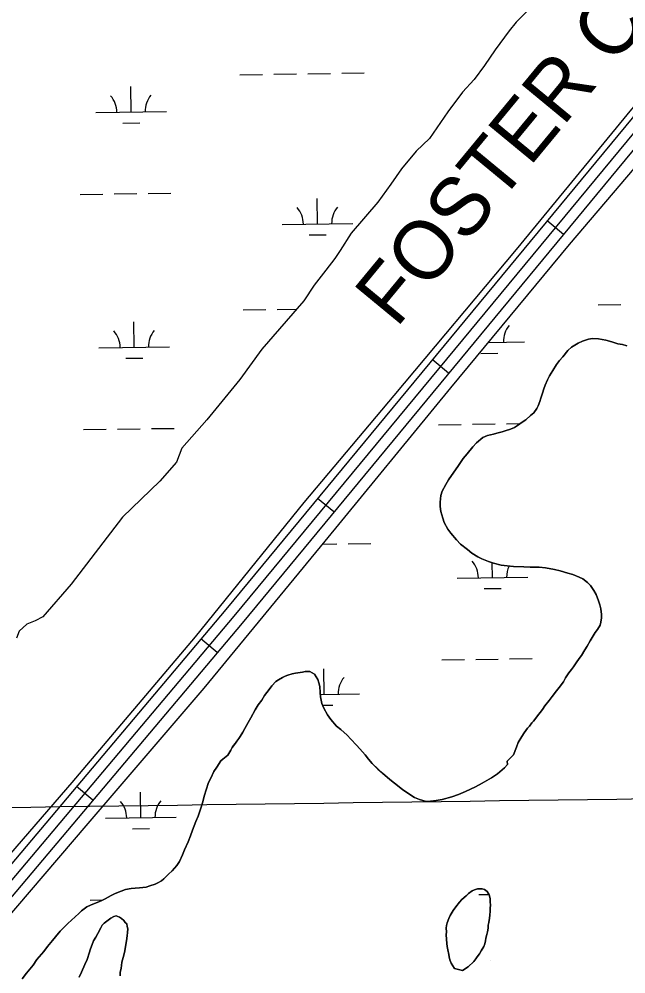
# Model space of a CAD drawing. Extents: x 3767014 to 3805179, y 361544 to 387384.
# Drawn here: x 3780968 to 3781825, y 372923 to 374273 of the extents above; entities that cross this region are included whole.
import ezdxf

# ---------------------------------------------------------------- set-up
doc = ezdxf.new("R2010")
doc.units = 0
for name, color, linetype in [('V-GRID-MAJR', 7, 'Continuous'), ('V-RIVR-IDEN', 7, 'Continuous'), ('V-ROAD-CNTR', 7, 'Continuous'), ('V-TOPO-SHOR', 7, 'Continuous'), ('V-WETL-SWMP', 7, 'Continuous')]:
    doc.layers.add(name, color=color, linetype=linetype)

msp = doc.modelspace()

# ---------------------------------------------------------------- linework, layer by layer
at = {"layer": 'V-GRID-MAJR'}
msp.add_spline([(3771169.95, 373025.6), (3773820.257, 373061.356), (3779120.863, 373133.445), (3784421.458, 373206.305), (3789722.043, 373279.937), (3795022.617, 373354.339), (3800323.181, 373429.512), (3802973.458, 373467.388)], degree=3, dxfattribs=at)
at = {"layer": 'V-ROAD-CNTR'}
for p, q in [((3781737.115, 373968.938), (3781713.992, 373988.051)), ((3781574.851, 373772.623), (3781551.728, 373791.736)), ((3781412.587, 373576.31), (3781389.464, 373595.423)), ((3781247.511, 373377.399), (3781224.569, 373396.728)), ((3781071.641, 373168.645), (3781048.698, 373187.974))]:
    msp.add_line(p, q, dxfattribs=at)
for points in [[(3782996.008, 375549.581), (3782070.95, 374419.915), (3781259.697, 373438.426), (3780556.215, 372603.406), (3780262.248, 372247.669), (3780020.473, 371935.287), (3779872.046, 371735.835), (3779803.549, 371623.461)], [(3783007.613, 375540.078), (3782082.534, 374410.385), (3781271.214, 373428.815), (3780567.732, 372593.796), (3780273.963, 372238.299), (3780032.422, 371926.218), (3779884.493, 371727.436), (3779816.357, 371615.654)], [(3783019.218, 375530.575), (3782094.118, 374400.855), (3781282.731, 373419.204), (3780579.249, 372584.186), (3780285.678, 372228.93), (3780044.371, 371917.149), (3779896.94, 371719.037), (3779829.165, 371607.847)], [(3781633.577, 372941.884), (3781633.577, 372941.884)]]:
    msp.add_lwpolyline(points, dxfattribs=at)
at = {"layer": 'V-TOPO-SHOR'}
for points in [[(3781687.181, 374286.085), (3781670.508, 374269.162), (3781660.483, 374256.846), (3781640.689, 374229.976), (3781625.632, 374207.759), (3781610.797, 374187.926), (3781594.419, 374170.041), (3781573.801, 374142.08), (3781548.005, 374104.54), (3781528.764, 374086.731), (3781508.061, 374061.634), (3781493.172, 374039.733), (3781474.533, 374014.426), (3781437.118, 373970.82), (3781421.522, 373946.23), (3781414.07, 373934.959), (3781401.225, 373918.258), (3781384.914, 373896.871), (3781370.021, 373874.81), (3781310.808, 373806.771), (3781279.608, 373763.482), (3781232.934, 373706.425), (3781197.688, 373666.741), (3781190.166, 373646.56), (3781166.718, 373619.944), (3781113.833, 373568.935), (3781041.197, 373474.184), (3781001.172, 373428.096), (3780990.203, 373422.488), (3780978.62, 373417.692), (3780967.858, 373407.782), (3780963.946, 373398.015)], [(3780018.581, 371950.259), (3780033.478, 371966.27), (3780045.985, 371982.185), (3780060.432, 371999.163), (3780088.952, 372037.428), (3780171.11, 372137.188), (3780262.123, 372259.482), (3780354.5, 372372.989), (3780473.141, 372511.126), (3780614.631, 372677.33), (3780714.029, 372797.658), (3780803.323, 372908.852), (3780910.522, 373041.556), (3781042.571, 373193.516), (3781216.921, 373399.622), (3781370.644, 373589.706), (3781497.896, 373740.834), (3781670.832, 373947.614), (3781833.678, 374145.897), (3781903.857, 374225.591), (3781920.876, 374243.62), (3781934.567, 374256.002), (3781951.979, 374270.833), (3781963.1, 374282.327)], [(3781701.369, 373726.637), (3781703.692, 373732.76), (3781705.045, 373737.362), (3781707.702, 373744.405), (3781709.397, 373750.236), (3781711.386, 373755.442), (3781714.683, 373763.396), (3781717.299, 373768.895), (3781722.132, 373776.5), (3781727.291, 373784.716), (3781731.768, 373790.475), (3781736.237, 373795.927), (3781743.572, 373804.705), (3781748.643, 373809.519), (3781758.058, 373814.844), (3781764.317, 373817.775), (3781772.431, 373820.659), (3781778.325, 373821.435), (3781786.666, 373821.22), (3781791.895, 373820.157), (3781797.126, 373819.096), (3781805.721, 373816.71), (3781814.317, 373814.324), (3781820.473, 373813.239), (3781826.605, 373811.225)], [(3781635.569, 373200.223), (3781643.755, 373205.888), (3781653.872, 373214.594), (3781658.009, 373219.124), (3781657.509, 373223.775), (3781666.709, 373232.815), (3781670.705, 373243.843), (3781673.342, 373250.268), (3781678.51, 373258.794), (3781681.733, 373263.965), (3781686.536, 373270.336), (3781689.397, 373273.353), (3781692.606, 373277.91), (3781694.832, 373280.326), (3781698.351, 373284.873), (3781700.593, 373287.906), (3781704.427, 373292.756), (3781707.628, 373297.001), (3781710.854, 373302.175), (3781716.916, 373309.441), (3781721.393, 373315.2), (3781727.477, 373323.392), (3781731.313, 373328.239), (3781737.082, 373336.13), (3781740.007, 373341.621), (3781744.832, 373348.916), (3781748.66, 373353.456), (3781751.543, 373357.403), (3781755.394, 373362.867), (3781759.569, 373368.945), (3781762.779, 373373.5), (3781767.614, 373381.107), (3781770.837, 373386.28), (3781775.052, 373393.9), (3781777.96, 373398.773), (3781782.161, 373405.777), (3781785.362, 373410.022), (3781788.919, 373416.115), (3781789.96, 373420.418), (3781791.045, 373426.572), (3781790.855, 373431.217), (3781789.827, 373439.282), (3781788.424, 373444.883), (3781786.722, 373450.802), (3781783.236, 373459.549), (3781780.289, 373465.189), (3781775.218, 373472.433), (3781770.995, 373476.56), (3781764.634, 373481.672), (3781759.444, 373484.279), (3781750.573, 373487.908), (3781743.513, 373489.943), (3781732.769, 373493.003), (3781724.467, 373494.762), (3781711.853, 373497.253), (3781702.909, 373498.101), (3781690.241, 373498.426), (3781681.281, 373498.658), (3781666.756, 373499.03), (3781657.511, 373500.196), (3781649.184, 373501.029), (3781638.123, 373503.788), (3781631.381, 373506.125), (3781621.899, 373510.079), (3781616.093, 373512.703), (3781607.884, 373518.171), (3781601.523, 373523.281), (3781591.826, 373530.95), (3781586.106, 373536.974), (3781577.994, 373546.149), (3781573.511, 373552.137), (3781568.495, 373561.544), (3781566.793, 373567.462), (3781563.949, 373577.121), (3781562.888, 373583.949), (3781562.738, 373590.138), (3781563.903, 373599.382), (3781565.917, 373605.514), (3781570.805, 373615.283), (3781574.688, 373621.986), (3781582.383, 373632.609), (3781587.843, 373640.508), (3781595.551, 373651.75), (3781600.989, 373658.721), (3781609.277, 373668.402), (3781614.37, 373674.147), (3781623.222, 373681.648), (3781629.781, 373684.264), (3781638.498, 373686.512), (3781643.171, 373687.938), (3781650.325, 373689.609), (3781655.001, 373691.034), (3781662.488, 373693.625), (3781667.805, 373695.962), (3781672.202, 373698.63), (3781678.819, 373703.408), (3781683.851, 373706.679), (3781690.806, 373712.684), (3781695.236, 373716.589), (3781699.411, 373722.668), (3781701.369, 373726.637)], [(3781089.032, 373029.387), (3781097.494, 373033.807), (3781103.443, 373036.746), (3781111.881, 373040.239), (3781117.808, 373042.251), (3781125.881, 373043.59), (3781131.775, 373044.364), (3781137.661, 373044.831), (3781146.963, 373045.83), (3781152.266, 373047.549), (3781159.745, 373049.828), (3781163.499, 373051.587), (3781168.832, 373054.543), (3781172.309, 373057.545), (3781178.656, 373063.875), (3781184.045, 373068.993), (3781190.725, 373076.241), (3781194.274, 373082.025), (3781198.538, 373091.501), (3781201.493, 373098.227), (3781206.431, 373109.849), (3781209.735, 373118.113), (3781212.723, 373126.073), (3781217.368, 373138.322), (3781220.657, 373145.967), (3781224.357, 373157.623), (3781226.711, 373164.981), (3781229.77, 373175.725), (3781232.132, 373183.395), (3781235.484, 373193.512), (3781238.732, 373199.613), (3781242.996, 373209.087), (3781247.18, 373215.472), (3781252.663, 373224.297), (3781255.817, 373226.691), (3781262.766, 373232.387), (3781266.966, 373239.389), (3781268.916, 373243.051), (3781270.841, 373245.785), (3781273.716, 373249.42), (3781275.332, 373252.16), (3781278.21, 373255.798), (3781280.143, 373258.841), (3781283.7, 373264.932), (3781286.617, 373270.113), (3781291.474, 373278.645), (3781295.349, 373285.039), (3781301.204, 373296.33), (3781305.714, 373303.323), (3781310.84, 373310.303), (3781314.715, 373316.697), (3781321.117, 373325.19), (3781324.652, 373330.355), (3781330.681, 373336.384), (3781334.454, 373338.76), (3781340.11, 373342.326), (3781343.866, 373344.085), (3781347.614, 373345.533), (3781353.848, 373347.538), (3781358.198, 373348.353), (3781364.719, 373349.422), (3781368.133, 373349.952), (3781372.176, 373350.776), (3781378.664, 373350.61), (3781385.058, 373346.735), (3781390.118, 373339.184), (3781391.245, 373334.826), (3781392.654, 373329.534), (3781393.057, 373321.174), (3781393.508, 373314.669), (3781395.433, 373305.345), (3781398.355, 373298.777), (3781403.678, 373289.362), (3781408.456, 373282.747), (3781416.259, 373273.58), (3781422.62, 373268.469), (3781431.381, 373260.514), (3781436.801, 373254.808), (3781444.628, 373246.567), (3781449.437, 373241.187), (3781456.637, 373232.653), (3781461.739, 373226.648), (3781466.843, 373220.644), (3781474.985, 373212.704), (3781481.33, 373206.973), (3781491.613, 373198.052), (3781498.277, 373192.625), (3781509.795, 373183.671), (3781517.084, 373178.537), (3781526.82, 373172.411), (3781533.554, 373169.763), (3781543.071, 373167.045), (3781549.197, 373167.197), (3781557.139, 373168.229), (3781565.53, 373169.87), (3781579.538, 373173.527), (3781588.893, 373176.687), (3781598.584, 373180.767), (3781612.982, 373187.509), (3781622.077, 373192.531), (3781635.569, 373200.223)], [(3781594.673, 372927.761), (3781602.539, 372933.125), (3781610.463, 372940.651), (3781613.338, 372944.287), (3781615.273, 372947.33), (3781618.474, 372951.575), (3781621.057, 372955.837), (3781624.606, 372961.621), (3781626.257, 372965.598), (3781626.986, 372969.907), (3781627.381, 372973.299), (3781628.751, 372978.521), (3781629.784, 372982.512), (3781630.535, 372987.749), (3781630.949, 372991.759), (3781631.67, 372995.761), (3781632.747, 373001.608), (3781633.169, 373005.925), (3781633.628, 373011.789), (3781633.716, 373015.186), (3781633.865, 373021.058), (3781633.638, 373024.157), (3781633.771, 373029.408), (3781632.362, 373034.702), (3781629.401, 373039.723), (3781625.446, 373042.3), (3781622.38, 373043.305), (3781615.575, 373043.172), (3781611.517, 373041.73), (3781608.079, 373040.272), (3781602.732, 373036.701), (3781599.553, 373033.381), (3781593.548, 373028.279), (3781590.044, 373024.349), (3781584.934, 373017.988), (3781581.092, 373012.831), (3781577.201, 373005.819), (3781574.92, 373001.239), (3781572.605, 372995.425), (3781571.882, 372991.423), (3781571.479, 372987.725), (3781571.653, 372982.463), (3781571.549, 372978.445), (3781572.007, 372972.25), (3781572.466, 372966.055), (3781572.974, 372961.713), (3781573.781, 372957.054), (3781575.159, 372950.527), (3781575.38, 372947.119), (3781576.507, 372942.761), (3781578.549, 372938.071), (3781580.625, 372934.616), (3781582.995, 372930.536), (3781594.673, 372927.761)], [(3780972.023, 372916.141), (3780978.102, 372924.024), (3780987.365, 372935.533), (3780992.823, 372943.433), (3781002.387, 372954.627), (3781007.822, 372961.598), (3781014.851, 372970.384), (3781019.002, 372975.535), (3781025.699, 372983.399), (3781030.152, 372988.233), (3781036.808, 372994.555), (3781041.237, 372998.46), (3781047.259, 373004.18), (3781051.688, 373008.086), (3781055.815, 373012.309), (3781063.383, 373017.988), (3781068.699, 373020.325), (3781074.325, 373022.653), (3781078.073, 373024.103), (3781084.633, 373026.717), (3781089.032, 373029.387)], [(3781119.711, 372993.596), (3781117.476, 372995.695), (3781115.385, 372998.593), (3781112.242, 373001.334), (3781109.387, 373003.386), (3781104.674, 373005.301), (3781101.434, 373004.334), (3781097.166, 373001.907), (3781093.511, 372999.218), (3781087.641, 372994.608), (3781084.975, 372991.894), (3781082.963, 372988.235), (3781078.732, 372979.995), (3781075.822, 372975.123), (3781072.9, 372969.633), (3781068.247, 372957.076), (3781067.233, 372953.701), (3781063.573, 372943.592), (3781060.599, 372936.246), (3781055.68, 372925.242), (3781052.405, 372918.216)], [(3781110.282, 372920.374), (3781110.339, 372925.072), (3781111.732, 372931.097), (3781112.391, 372935.099), (3781112.694, 372939.668), (3781115.672, 372949.609), (3781117.003, 372955.698), (3781118.472, 372964.689), (3781119.16, 372969.803), (3781120.204, 372976.764), (3781120.94, 372981.321), (3781121.079, 372986.699), (3781120.54, 372989.803), (3781119.711, 372993.596)]]:
    msp.add_lwpolyline(points, dxfattribs=at)
at = {"layer": 'V-WETL-SWMP'}
for p, q in [((3781279.674, 374194.754), (3781311.671, 374195.198)), ((3781327.669, 374195.42), (3781359.666, 374195.865)), ((3781375.665, 374196.087), (3781407.661, 374196.531)), ((3781423.66, 374196.754), (3781455.657, 374197.198)), ((3781125.801, 374141.869), (3781125.301, 374177.866)), ((3781075.806, 374141.175), (3781175.797, 374142.564)), ((3781577.666, 374148.146), (3781578.282, 374148.155)), ((3781114.017, 374126.273), (3781138.015, 374126.606)), ((3781054.004, 374025.429), (3781086.001, 374025.873)), ((3781101.999, 374026.095), (3781133.996, 374026.54)), ((3781149.995, 374026.762), (3781181.992, 374027.207)), ((3781389.461, 373983.654), (3781388.96, 374019.651)), ((3781339.465, 373982.96), (3781439.456, 373984.349)), ((3781377.676, 373968.058), (3781401.674, 373968.391)), ((3781786.154, 373869.082), (3781818.151, 373869.527)), ((3781284.295, 373862.111), (3781316.291, 373862.555)), ((3781332.29, 373862.777), (3781359.883, 373863.161)), ((3781130.422, 373809.226), (3781129.922, 373845.223)), ((3781631.211, 373816.183), (3781682.277, 373816.892)), ((3781632.282, 373816.198), (3781632.264, 373817.456)), ((3781080.427, 373808.532), (3781180.417, 373809.921)), ((3781620.497, 373800.602), (3781644.495, 373800.935)), ((3781118.638, 373793.63), (3781142.635, 373793.963)), ((3781058.625, 373692.786), (3781090.622, 373693.23)), ((3781106.62, 373693.453), (3781138.617, 373693.897)), ((3781154.615, 373694.119), (3781186.612, 373694.564)), ((3781560.484, 373699.757), (3781592.481, 373700.202)), ((3781608.48, 373700.424), (3781640.477, 373700.868)), ((3781656.475, 373701.091), (3781675.984, 373701.362)), ((3781397.107, 373530.971), (3781416.903, 373531.246)), ((3781432.902, 373531.468), (3781464.898, 373531.912)), ((3781636.903, 373483.555), (3781636.614, 373504.311)), ((3781586.908, 373482.86), (3781686.898, 373484.249)), ((3781625.118, 373467.959), (3781649.116, 373468.292)), ((3781565.105, 373367.114), (3781597.102, 373367.559)), ((3781613.1, 373367.781), (3781645.097, 373368.226)), ((3781661.096, 373368.448), (3781693.093, 373368.892)), ((3781398.702, 373318.368), (3781398.202, 373354.365)), ((3781393.257, 373318.293), (3781448.697, 373319.063)), ((3781396.517, 373302.906), (3781410.915, 373303.106)), ((3781139.664, 373143.941), (3781139.164, 373179.937)), ((3781089.669, 373143.246), (3781189.659, 373144.635)), ((3781127.879, 373128.344), (3781151.877, 373128.678)), ((3781601.014, 373034.906), (3781601.723, 373034.916)), ((3781617.721, 373035.138), (3781631.987, 373035.336)), ((3781067.866, 373027.5), (3781086.346, 373027.757))]:
    msp.add_line(p, q, dxfattribs=at)
for points in [[(3781687.181, 374286.084), (3781670.509, 374269.162), (3781660.483, 374256.845), (3781640.69, 374229.976), (3781625.633, 374207.76), (3781610.797, 374187.926), (3781594.419, 374170.042), (3781573.802, 374142.079), (3781548.004, 374104.54), (3781528.763, 374086.73), (3781508.061, 374061.635), (3781493.171, 374039.733), (3781474.533, 374014.426), (3781437.118, 373970.819), (3781421.523, 373946.229), (3781414.07, 373934.96), (3781401.224, 373918.258), (3781384.915, 373896.871), (3781370.021, 373874.81), (3781310.807, 373806.772), (3781279.609, 373763.483), (3781232.934, 373706.425), (3781197.689, 373666.741), (3781190.166, 373646.56), (3781166.719, 373619.944)], [(3780025.717, 371834.653), (3780056.527, 371895), (3780166.581, 372039.392), (3780290.996, 372202.544), (3780433.66, 372382.481), (3780595.159, 372572.811), (3780741.306, 372749.657), (3780921.136, 372967.272), (3781065.005, 373135.738), (3781228.964, 373326.942), (3781400.292, 373534.835), (3781578.045, 373751.941), (3781745.672, 373954.491), (3781888.974, 374122.784), (3782009.425, 374259.986), (3782010.435, 374249.773), (3782030.835, 374226.008), (3782094.59, 374167.381), (3782154.079, 374116.187), (3782194.889, 374081.391), (3782251.034, 374036.331), (3782277.797, 374012.402), (3782296.183, 373996.966), (3782313.044, 373984.117)], [(3781826.605, 373811.225), (3781820.473, 373813.238), (3781814.317, 373814.324), (3781805.721, 373816.709), (3781797.125, 373819.095), (3781791.896, 373820.157), (3781786.667, 373821.219), (3781778.324, 373821.434), (3781772.43, 373820.658), (3781764.316, 373817.775), (3781758.057, 373814.844), (3781748.644, 373809.52), (3781743.573, 373804.704), (3781736.236, 373795.926), (3781731.767, 373790.475), (3781727.29, 373784.716), (3781722.131, 373776.5), (3781717.298, 373768.895), (3781714.683, 373763.397), (3781711.386, 373755.442), (3781709.397, 373750.237), (3781707.701, 373744.406), (3781705.046, 373737.363), (3781703.691, 373732.76), (3781701.369, 373726.636), (3781699.412, 373722.667), (3781695.236, 373716.59), (3781690.806, 373712.684), (3781683.85, 373706.68), (3781678.818, 373703.408), (3781672.202, 373698.631), (3781667.805, 373695.961), (3781662.488, 373693.625), (3781655.001, 373691.035), (3781650.326, 373689.609), (3781643.172, 373687.938), (3781638.497, 373686.512), (3781629.782, 373684.263), (3781623.222, 373681.649), (3781614.371, 373674.147), (3781609.276, 373668.403), (3781600.988, 373658.722), (3781595.552, 373651.75), (3781587.842, 373640.509), (3781582.383, 373632.61), (3781574.689, 373621.986), (3781570.806, 373615.284), (3781565.917, 373605.515), (3781563.904, 373599.383), (3781562.738, 373590.137), (3781562.888, 373583.949), (3781563.949, 373577.12), (3781566.793, 373567.462), (3781568.496, 373561.543), (3781573.51, 373552.138), (3781577.994, 373546.148), (3781586.106, 373536.973), (3781591.826, 373530.951), (3781601.523, 373523.281), (3781607.884, 373518.17), (3781616.092, 373512.702), (3781621.899, 373510.079), (3781631.382, 373506.125), (3781638.124, 373503.787), (3781649.184, 373501.029), (3781657.511, 373500.196), (3781666.757, 373499.031), (3781681.28, 373498.657), (3781690.241, 373498.427), (3781702.909, 373498.101), (3781711.854, 373497.252), (3781724.467, 373494.763), (3781732.77, 373493.003), (3781743.513, 373489.944), (3781750.572, 373487.907), (3781759.445, 373484.278), (3781764.635, 373481.671), (3781770.996, 373476.56), (3781775.219, 373472.432), (3781780.289, 373465.19), (3781783.236, 373459.549), (3781786.721, 373450.801), (3781788.424, 373444.883), (3781789.826, 373439.281), (3781790.855, 373431.216), (3781791.045, 373426.573), (3781789.959, 373420.417), (3781788.92, 373416.115), (3781785.362, 373410.023), (3781782.161, 373405.776), (3781777.961, 373398.773), (3781775.053, 373393.901), (3781770.838, 373386.279), (3781767.613, 373381.106), (3781762.779, 373373.5), (3781759.57, 373368.945)], [(3781166.719, 373619.944), (3781113.833, 373568.935), (3781041.197, 373474.183), (3781001.172, 373428.096), (3780990.203, 373422.488), (3780978.619, 373417.693), (3780967.858, 373407.782), (3780963.946, 373398.014)], [(3781759.57, 373368.945), (3781755.394, 373362.868), (3781751.543, 373357.402), (3781748.659, 373353.457), (3781744.831, 373348.917), (3781740.006, 373341.621), (3781737.082, 373336.13), (3781731.313, 373328.24), (3781727.478, 373323.391), (3781721.393, 373315.2), (3781716.916, 373309.44), (3781710.854, 373302.175), (3781707.629, 373297.002), (3781704.428, 373292.756), (3781700.593, 373287.907), (3781698.35, 373284.873), (3781694.832, 373280.326), (3781692.606, 373277.909), (3781689.396, 373273.354), (3781686.536, 373270.336), (3781681.734, 373263.966), (3781678.509, 373258.793), (3781673.343, 373250.268), (3781670.704, 373243.843), (3781666.71, 373232.815), (3781657.51, 373223.776), (3781658.009, 373219.125), (3781653.873, 373214.593), (3781643.755, 373205.887), (3781635.57, 373200.223), (3781622.076, 373192.531), (3781612.981, 373187.509), (3781598.584, 373180.768), (3781588.894, 373176.688), (3781579.537, 373173.528), (3781565.529, 373169.869), (3781557.138, 373168.229), (3781549.196, 373167.197), (3781543.071, 373167.045), (3781533.555, 373169.764), (3781526.821, 373172.411), (3781517.085, 373178.536), (3781509.796, 373183.671), (3781498.277, 373192.624), (3781491.614, 373198.052), (3781481.331, 373206.974), (3781474.986, 373212.703), (3781466.842, 373220.643), (3781461.74, 373226.649), (3781456.638, 373232.654), (3781449.437, 373241.188), (3781444.628, 373246.568), (3781436.801, 373254.809), (3781431.382, 373260.514), (3781422.62, 373268.469), (3781416.259, 373273.58), (3781408.456, 373282.747), (3781403.679, 373289.363), (3781398.355, 373298.776), (3781395.432, 373305.344), (3781393.508, 373314.67), (3781393.057, 373321.174), (3781392.654, 373329.533), (3781391.244, 373334.826), (3781390.119, 373339.183), (3781385.057, 373346.734), (3781378.664, 373350.609), (3781372.175, 373350.776), (3781368.134, 373349.953), (3781364.719, 373349.422), (3781358.199, 373348.353), (3781353.849, 373347.537), (3781347.614, 373345.533), (3781343.866, 373344.084), (3781340.11, 373342.325), (3781334.453, 373338.761), (3781330.682, 373336.384), (3781324.652, 373330.355), (3781321.118, 373325.19), (3781314.715, 373316.697), (3781310.84, 373310.304), (3781305.714, 373303.324), (3781301.205, 373296.329), (3781295.349, 373285.039), (3781291.474, 373278.646), (3781286.617, 373270.113), (3781283.701, 373264.932), (3781280.143, 373258.84), (3781278.209, 373255.797), (3781275.333, 373252.161), (3781273.716, 373249.42), (3781270.84, 373245.784), (3781268.915, 373243.05), (3781266.965, 373239.39), (3781262.765, 373232.387), (3781255.817, 373226.691), (3781252.663, 373224.298), (3781247.18, 373215.473), (3781242.996, 373209.087), (3781238.732, 373199.612), (3781235.484, 373193.512)], [(3781235.484, 373193.512), (3781232.131, 373183.394), (3781229.77, 373175.725), (3781226.71, 373164.982), (3781224.357, 373157.622), (3781220.656, 373145.968), (3781217.367, 373138.323), (3781212.723, 373126.074), (3781209.735, 373118.112), (3781206.431, 373109.849), (3781201.494, 373098.226), (3781198.538, 373091.5), (3781194.275, 373082.025), (3781190.725, 373076.241), (3781184.045, 373068.993), (3781178.657, 373063.875), (3781172.31, 373057.545), (3781168.832, 373054.543), (3781163.5, 373051.588), (3781159.744, 373049.829), (3781152.265, 373047.548), (3781146.964, 373045.83), (3781137.662, 373044.832), (3781131.776, 373044.365), (3781125.881, 373043.589), (3781117.808, 373042.251), (3781111.881, 373040.239), (3781103.443, 373036.746), (3781097.493, 373033.807), (3781089.031, 373029.387), (3781084.633, 373026.717), (3781078.073, 373024.103), (3781074.325, 373022.654), (3781068.7, 373020.325), (3781063.383, 373017.988), (3781055.816, 373012.308), (3781051.688, 373008.086), (3781047.259, 373004.18), (3781041.237, 372998.46), (3781036.808, 372994.555), (3781030.152, 372988.233), (3781025.699, 372983.4), (3781019.003, 372975.534), (3781014.851, 372970.384), (3781007.823, 372961.598), (3781002.387, 372954.627), (3780992.823, 372943.432), (3780987.364, 372935.534), (3780978.101, 372924.023), (3780972.023, 372916.14)], [(3781052.406, 372918.216), (3781055.679, 372925.243), (3781060.6, 372936.247), (3781063.572, 372943.592), (3781067.233, 372953.701), (3781068.247, 372957.076), (3781072.899, 372969.633), (3781075.823, 372975.124), (3781078.732, 372979.996), (3781082.963, 372988.235), (3781084.974, 372991.894), (3781087.641, 372994.608), (3781093.511, 372999.219), (3781097.167, 373001.907), (3781101.434, 373004.333), (3781104.675, 373005.301), (3781109.387, 373003.386), (3781112.241, 373001.334), (3781115.386, 372998.594), (3781117.476, 372995.695), (3781119.71, 372993.597), (3781120.54, 372989.804), (3781121.078, 372986.698), (3781120.94, 372981.321), (3781120.204, 372976.764), (3781119.159, 372969.803), (3781118.471, 372964.688), (3781117.003, 372955.698), (3781115.672, 372949.61), (3781112.695, 372939.669), (3781112.392, 372935.1), (3781111.732, 372931.098), (3781110.34, 372925.073), (3781110.281, 372920.375)]]:
    msp.add_lwpolyline(points, dxfattribs=at)
msp.add_lwpolyline([(3781594.672, 372927.762), (3781582.994, 372930.536), (3781580.625, 372934.616), (3781578.549, 372938.071), (3781576.506, 372942.761), (3781575.381, 372947.119), (3781575.16, 372950.526), (3781573.782, 372957.054), (3781572.974, 372961.713), (3781572.467, 372966.055), (3781572.008, 372972.25), (3781571.549, 372978.446), (3781571.653, 372982.463), (3781571.479, 372987.724), (3781571.883, 372991.424), (3781572.605, 372995.425), (3781574.919, 373001.24), (3781577.201, 373005.819), (3781581.092, 373012.831), (3781584.935, 373017.988), (3781590.045, 373024.35), (3781593.548, 373028.279), (3781599.554, 373033.381), (3781602.731, 373036.7), (3781608.079, 373040.273), (3781611.518, 373041.73), (3781615.575, 373043.172), (3781622.38, 373043.306), (3781625.446, 373042.3), (3781629.4, 373039.724), (3781632.362, 373034.701), (3781633.772, 373029.408), (3781633.637, 373024.156), (3781633.866, 373021.058), (3781633.715, 373015.187), (3781633.628, 373011.788), (3781633.168, 373005.925), (3781632.748, 373001.607), (3781631.67, 372995.76), (3781630.948, 372991.759), (3781630.536, 372987.75), (3781629.783, 372982.513), (3781628.752, 372978.52), (3781627.381, 372973.299), (3781626.985, 372969.908), (3781626.256, 372965.598), (3781624.607, 372961.621), (3781621.057, 372955.838), (3781618.474, 372951.576), (3781615.273, 372947.329), (3781613.339, 372944.287), (3781610.463, 372940.651), (3781602.539, 372933.125)], close=True, dxfattribs=at)
for centre, start, end in [((3781070.557, 374141.577), 0.024037, 41.567696), ((3781181.032, 374143.111), 140.024034, 181.567693), ((3781334.216, 373983.362), 0.024037, 41.567696), ((3781444.692, 373984.896), 140.024034, 181.567693), ((3781075.178, 373808.934), 0.024037, 41.567696), ((3781185.653, 373810.468), 140.024034, 181.567693), ((3781687.513, 373817.44), 140.024034, 181.567693), ((3781581.658, 373483.262), 0.024037, 41.567696), ((3781692.134, 373484.797), 154.718853, 181.567693), ((3781453.933, 373319.61), 140.024034, 181.567693), ((3781084.42, 373143.648), 0.024037, 41.567696), ((3781194.895, 373145.183), 140.024034, 181.567693)]:
    msp.add_arc(centre, 35.246, start, end, dxfattribs=at)

# ---------------------------------------------------------------- texts
at = {"layer": 'V-RIVR-IDEN'}
msp.add_text('FOSTER CANAL', height=83, rotation=50.469072, dxfattribs=at).set_placement((3781500.967, 373835.134))

doc.saveas('drawing.dxf')
